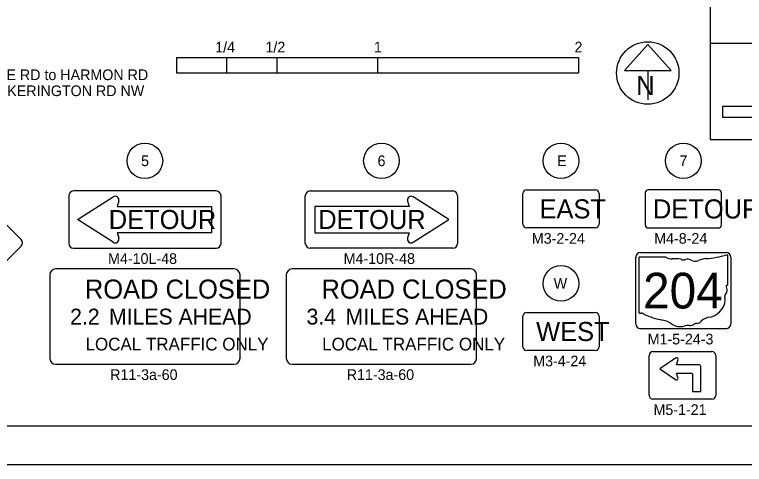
# Model space of a CAD drawing. Extents: x 1880545 to 1948545, y 79309 to 723051.
# Drawn here: x 1902373 to 1921540, y 679051 to 690858 of the extents above; entities that cross this region are included whole.
import ezdxf

# ---------------------------------------------------------------- set-up
doc = ezdxf.new("R2010")
doc.units = 0
for name, color, linetype in [('SH_Border', 7, 'Continuous'), ('SH_Cut_Line', 7, 'Continuous'), ('SH_Masking', 7, 'Continuous'), ('SH_Text', 7, 'Continuous'), ('SN_P_Signs', 7, 'Continuous'), ('SN_P_Text', 7, 'Continuous'), ('UT_P_Electric', 7, 'Continuous')]:
    doc.layers.add(name, color=color, linetype=linetype)

msp = doc.modelspace()

# ---------------------------------------------------------------- linework, layer by layer
at = {"layer": 'SH_Border'}
msp.add_lwpolyline([(1883545, 722051), (1947545, 722051), (1947545, 680051), (1883545, 680051)], close=True, dxfattribs=at)
at = {"layer": 'SH_Cut_Line'}
msp.add_lwpolyline([(1880545, 679051), (1948545, 679051), (1948545, 723051), (1880545, 723051)], close=True, dxfattribs=at)
at = {"layer": 'SH_Masking'}
msp.add_circle((1919002, 689326), 820, dxfattribs=at)
at = {"layer": 'SH_Text'}
for p, q in [((1920641, 691152), (1920641, 687581)), ((1919002, 690074), (1918387, 689391)), ((1919617, 689391), (1919002, 690074)), ((1920641, 690105), (1928141, 690105)), ((1906622, 689729), (1907942, 689729)), ((1906622, 689729), (1906622, 689329)), ((1907942, 689729), (1909262, 689729)), ((1907942, 689729), (1907942, 689329)), ((1909262, 689729), (1911902, 689729)), ((1909262, 689729), (1909262, 689329)), ((1911902, 689729), (1917182, 689729)), ((1911902, 689729), (1911902, 689329)), ((1917182, 689729), (1917182, 689329)), ((1906622, 689329), (1907942, 689329)), ((1907942, 689329), (1909262, 689329)), ((1909262, 689329), (1911902, 689329)), ((1911902, 689329), (1917182, 689329)), ((1918387, 689391), (1919617, 689391)), ((1919002, 689391), (1919002, 688618)), ((1920973, 688309), (1920973, 688459)), ((1920973, 688459), (1922473, 688459)), ((1920973, 688159), (1920973, 688309)), ((1922473, 688159), (1920973, 688159)), ((1920641, 687581), (1928141, 687581))]:
    msp.add_line(p, q, dxfattribs=at)
for centre, radius in [((1919002, 689326), 820), ((1905794, 687020), 468), ((1912008, 687020), 468), ((1916722, 687020), 468), ((1919935, 687020), 468), ((1916722, 683802), 468)]:
    msp.add_circle(centre, radius, dxfattribs=at)
at = {"layer": 'SN_P_Signs'}
for p, q in [((1918763, 684467), (1918763, 683044)), ((1919473, 684491), (1918786, 684491)), ((1921107, 683782), (1921107, 684526)), ((1921107, 683782), (1921107, 683782))]:
    msp.add_line(p, q, dxfattribs=at)
for points in [[(1918685, 682739), (1918685, 684489)], [(1918810, 684614), (1921060, 684614)], [(1921185, 684489), (1921185, 682739)], [(1908138, 684181), (1903450, 684181)], [(1914352, 684181), (1909664, 684181)], [(1903294, 684025), (1903294, 681837)], [(1908294, 681837), (1908294, 684025)], [(1909508, 684025), (1909508, 681837)], [(1914508, 681837), (1914508, 684025)], [(1921060, 682614), (1918810, 682614)], [(1903450, 681681), (1908138, 681681)], [(1909664, 681681), (1914352, 681681)]]:
    msp.add_lwpolyline(points, dxfattribs=at)
for centre, radius, start, end in [((1918810, 684489), 125, 90, 180), ((1921060, 684489), 125, 0, 90), ((1903450, 684025), 156, 90, 180), ((1908138, 684025), 156, 0, 90), ((1909664, 684025), 156, 90, 180), ((1914352, 684025), 156, 0, 90), ((1918810, 682739), 125, 180, 270), ((1921060, 682739), 125, 270, 0), ((1903450, 681837), 156, 180, 270), ((1908138, 681837), 156, 270, 0), ((1909664, 681837), 156, 180, 270), ((1914352, 681837), 156, 270, 0)]:
    msp.add_arc(centre, radius, start, end, dxfattribs=at)
for centre, major_axis, start_param, end_param in [((1918790, 684470), (27.2, 0), 1.712693, 3.28349), ((1919636, 684656), (263, 0), 4.042523, 4.731795), ((1920272, 686431), (2485, 0), 4.814394, 5.042369), ((1921081, 684529), (26.1, 0), 6.141152, 7.989035), ((1919724, 683692), (945, 0), 1.404758, 1.657858), ((1919938, 684477), (76, 0), 3.836095, 5.185415), ((1920050, 684313), (158, 0), 0.950623, 2.079405), ((1920254, 684538), (190, 0), 4.081561, 5.145723), ((1920589, 684056), (500, 0), 1.699011, 2.107814), ((1921101, 683727), (40.4, 0), 1.883978, 3.671073), ((1920844, 683633), (242, 0), 5.934695, 6.695948), ((1921079, 683779), (27.9, 0), 5.05454, 6.418171), ((1921201, 683470), (176, 0), 2.387724, 3.262537), ((1920411, 683376), (622, 0), 5.101752, 6.440018), ((1918790, 683040), (27.4, 0), 3.00124, 4.508301), ((1918795, 683186), (209, 0), 4.665946, 4.897461), ((1918837, 682961), (75.4, 0), 0.519207, 1.627899), ((1919789, 684240), (1795, 0), 4.195997, 4.488961), ((1919254, 682404), (562, 0), 0.823519, 1.323587), ((1920093, 682848), (190, 0), 4.691044, 5.507374), ((1920265, 682710), (53.5, 0), 1.147584, 2.315152), ((1920242, 682906), (201, 0), 4.937069, 5.64225), ((1920674, 682644), (340, 0), 1.647645, 2.488434), ((1919861, 682954), (356, 0), 4.026481, 4.996735), ((1920067, 682462), (293, 0), 1.495662, 1.94098)]:
    msp.add_ellipse(centre, major_axis=major_axis, ratio=0.8, start_param=start_param, end_param=end_param, dxfattribs=at)
at = {"layer": 'UT_P_Electric'}
for p, q in [((1915822, 686258), (1917622, 686258)), ((1904023, 685478), (1904961, 686076)), ((1913779, 685478), (1912841, 686076)), ((1915722, 685358), (1915722, 686158)), ((1917722, 686158), (1917722, 685358)), ((1905110, 685961), (1905065, 685822)), ((1905065, 685822), (1907544, 685822)), ((1907544, 685822), (1907544, 685134)), ((1912737, 685822), (1910258, 685822)), ((1910258, 685822), (1910258, 685134)), ((1912692, 685961), (1912737, 685822)), ((1904961, 684881), (1904023, 685478)), ((1912841, 684881), (1913779, 685478)), ((1917622, 685258), (1915822, 685258)), ((1907544, 685134), (1905065, 685134)), ((1905065, 685134), (1905110, 684996)), ((1910258, 685134), (1912737, 685134)), ((1912737, 685134), (1912692, 684996)), ((1915722, 682140), (1915722, 682940)), ((1915822, 683040), (1917622, 683040)), ((1917722, 682940), (1917722, 682140)), ((1917622, 682040), (1915822, 682040)), ((1919136, 682013), (1920686, 682013)), ((1919036, 680863), (1919036, 681913)), ((1919726, 681839), (1919318, 681559)), ((1919755, 681669), (1919797, 681809)), ((1920786, 681913), (1920786, 680863)), ((1920349, 681669), (1919755, 681669)), ((1920349, 681669), (1920349, 681669)), ((1920396, 680966), (1920396, 681622)), ((1919318, 681559), (1919726, 681280)), ((1919797, 681309), (1919755, 681450)), ((1919755, 681450), (1920146, 681450)), ((1920177, 681419), (1920177, 680966)), ((1920177, 680966), (1920396, 680966)), ((1920686, 680763), (1919136, 680763))]:
    msp.add_line(p, q, dxfattribs=at)
for points in [[(1901306, 686192), (1902544, 684954)], [(1907669, 686228), (1903919, 686228)], [(1910133, 686228), (1913883, 686228)], [(1920855, 686258), (1919015, 686258)], [(1903794, 686103), (1903794, 684853)], [(1907794, 684853), (1907794, 686103)], [(1910008, 684853), (1910008, 686103)], [(1914008, 686103), (1914008, 684853)], [(1918935, 686178), (1918935, 685338)], [(1920935, 685338), (1920935, 686178)], [(1919015, 685258), (1920855, 685258)], [(1902544, 684777), (1901306, 683540)], [(1903919, 684728), (1907669, 684728)], [(1913883, 684728), (1910133, 684728)]]:
    msp.add_lwpolyline(points, dxfattribs=at)
for centre, radius, start, end in [((1903919, 686103), 125, 90, 180), ((1907669, 686103), 125, 0, 90), ((1910133, 686103), 125, 90, 180), ((1913883, 686103), 125, 0, 90), ((1915822, 686158), 100, 90, 180), ((1917622, 686158), 100, 0, 90), ((1919015, 686178), 80, 90, 180), ((1920855, 686178), 80, 0, 90), ((1905014, 685991), 100, 342.1811, 122.5109), ((1912788, 685991), 100, 57.4891, 197.8189), ((1915822, 685358), 100, 180, 270), ((1917622, 685358), 100, 270, 0), ((1919015, 685338), 80, 180, 270), ((1920855, 685338), 80, 270, 0), ((1902456, 684866), 125, 315, 45), ((1903919, 684853), 125, 180, 270), ((1905014, 684965), 100, 237.4891, 17.8189), ((1907669, 684853), 125, 270, 0), ((1910133, 684853), 125, 180, 270), ((1912788, 684965), 100, 162.1811, 302.5109), ((1913883, 684853), 125, 270, 360), ((1915822, 682939), 100, 90, 180), ((1917622, 682939), 100, 0, 90), ((1915822, 682139), 100, 180, 270), ((1917622, 682139), 100, 270, 0), ((1919136, 681913), 100, 90, 180), ((1920686, 681913), 100, 0, 90), ((1919755, 681809), 41.7, 0.0017, 134.9999), ((1920349, 681622), 46.9, 0, 90), ((1920146, 681419), 31.2, 0, 90), ((1919755, 681309), 41.7, 225.0001, 0.0017), ((1919136, 680863), 100, 180, 270), ((1920686, 680863), 100, 270, 360)]:
    msp.add_arc(centre, radius, start, end, dxfattribs=at)

# ---------------------------------------------------------------- texts
at = {"layer": 'SH_Text'}
for s, height, p in [('1/4', 280, (1907641, 689866)), ('1/2', 280, (1908961, 689866)), ('1', 280, (1911811, 689866)), ('2', 280, (1917078, 689866)), ('WESTBOUND: PICKERINGTON RD NW to REFUGEE RD to HARMON RD', 280, (1893213, 689139)), ('N', 500, (1918700, 688744)), ('EASTBOUND: HARMON RD to REFUGEE RD to PICKERINGTON RD NW', 280, (1893213, 688719)), ('5', 280, (1905695, 686880)), ('6', 280, (1911905, 686880)), ('E', 280, (1916625, 686880)), ('7', 280, (1919834, 686880)), ('W', 280, (1916532, 683662))]:
    msp.add_text(s, height=height, dxfattribs=at).set_placement(p)
at = {"layer": 'SN_P_Signs'}
for s, height, p in [('DETOUR', 500, (1904845, 685230)), ('DETOUR', 500, (1910346, 685230)), ('204', 937.5, (1918878, 683144)), ('ROAD CLOSED', 500, (1904219, 683403)), ('ROAD CLOSED', 500, (1910432, 683403)), ('2.2', 416.7, (1903831, 682722)), ('MILES AHEAD', 416.67, (1904852, 682722)), ('3.4', 416.7, (1910039, 682722)), ('MILES AHEAD', 416.67, (1911065, 682722)), ('LOCAL TRAFFIC ONLY', 333.33, (1904236, 682042)), ('LOCAL TRAFFIC ONLY', 333.33, (1910450, 682042))]:
    msp.add_text(s, height=height, dxfattribs=at).set_placement(p)
at = {"layer": 'SN_P_Text'}
for s, p in [('M3-2-24', (1915957, 684844)), ('M4-8-24', (1919171, 684844)), ('M4-10L-48', (1904828, 684314)), ('M4-10R-48', (1911015, 684314)), ('M1-5-24-3', (1918999, 682200)), ('M3-4-24', (1915993, 681626)), ('R11-3a-60', (1904883, 681267)), ('R11-3a-60', (1911096, 681267)), ('M5-1-21', (1919152, 680349))]:
    msp.add_text(s, height=280, dxfattribs=at).set_placement(p)
at = {"layer": 'UT_P_Electric'}
for s, p in [('EAST', (1916158, 685508)), ('DETOUR', (1919138, 685508)), ('WEST', (1916069, 682290))]:
    msp.add_text(s, height=500, dxfattribs=at).set_placement(p)

doc.saveas('drawing.dxf')
